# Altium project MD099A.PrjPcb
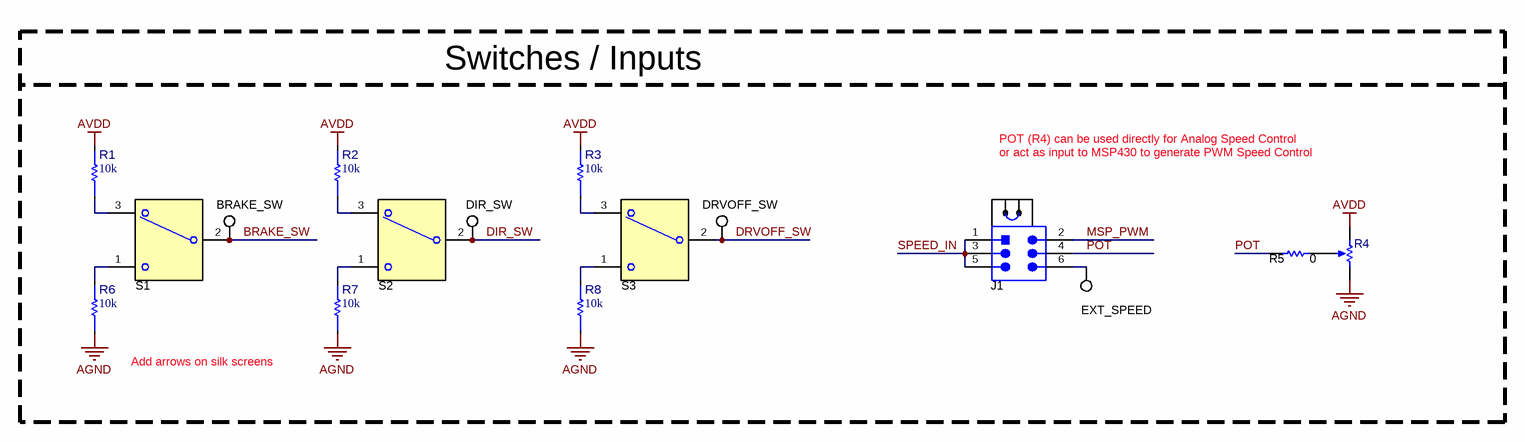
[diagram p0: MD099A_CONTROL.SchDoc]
TID: N/A; TechSupport: http://www.ti.com/support; SCH_Rev: Rev A; ProjectVariant: EVM_Orderable; PRJ_Title: MCF8315RRYEVM; PRJ_Number: MD099A; PRJ_Engineer: Andy Ampuero; PRJ_Customer: Public Release; PCB_Rev: Rev1.0; PCB_Layout: Andy Ampuero; CopyrightYear: 2024
5 sheets, 152 parts. Net scope: global (net labels, ports and power ports of the same name join across sheets).
Board file: MD099A.PcbDoc
Sheets:
  MD099A_CONTROL.SchDoc
  MD099A_DRIVER.SchDoc
  MD099A_HARDWARE.SchDoc
  MD099A_INTERFACE.SchDoc
  MD099A_POWER_AND_CONNECTORS.SchDoc

## Sheet MD099A_CONTROL.SchDoc
size 431 x 279 mm; Date: Not shown in title block; ApprovedBy: Not shown in title block; CheckedBy: Not shown in title block; Author: Not shown in title block; CompanyName: Not shown in title block; Engineer: Not shown in title block; Organization: Not shown in title block; Address1: Not shown in title block; Address2: Not shown in title block; Address3: Not shown in title block; Address4: Not shown in title block; DocumentNumber: 1; Revision: Use project parameter SCH_Rev; SheetNumber: 2; SheetTotal: 5; PageSetup: Record=PageOptions¦CenterHorizontal=True¦CenterVertical=True¦PrintScale=1.00¦XCorrection=1.00¦YCorrection=1.00¦PrintKind=0¦BorderSize=5000000¦LeftOffset=0¦BottomOffset=0¦Orientation=2¦PaperLength=1000¦PaperWidth=1000¦Scale=100¦PaperSource=15¦PrintQuality=600¦MediaType=1¦DitherType=10¦PaperKind=Letter¦PrintScaleMode=1

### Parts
J1  Header_3x2  [TSW-103-07-G-D]  (value not drawn)
R1  value 10k  [FP-ERA-3ARB103V_0603-MFG]  (hidden comment: ERA-3ARB103V)
R2  value 10k  [FP-ERA-3ARB103V_0603-MFG]  (hidden comment: ERA-3ARB103V)
R3  value 10k  [FP-ERA-3ARB103V_0603-MFG]  (hidden comment: ERA-3ARB103V)
R4  3352T-1-253LF  [Bourns_3352T]  (value not drawn)
R5  ValueDisplayed: 0  [0603L]  (hidden comment: ERJ-3GEY0R00V)
R6  value 10k  [FP-ERA-3ARB103V_0603-MFG]  (hidden comment: ERA-3ARB103V)
R7  value 10k  [FP-ERA-3ARB103V_0603-MFG]  (hidden comment: ERA-3ARB103V)
R8  value 10k  [FP-ERA-3ARB103V_0603-MFG]  (hidden comment: ERA-3ARB103V)
S1  SW_SPDT_COM2_1_3  [SW_B12AP]  (value not drawn)
S2  SW_SPDT_COM2_1_3  [SW_B12AP]  (value not drawn)
S3  SW_SPDT_COM2_1_3  [SW_B12AP]  (value not drawn)
SH-J1  SNT-100-BK-G  [SNT-100-BK-G]  (value not drawn)
TP1  BRAKE_SW  [Keystone5002]
TP2  DIR_SW  [Keystone5002]
TP3  DRVOFF_SW  [Keystone5002]
TP4  EXT_SPEED  [Keystone5002]

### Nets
AGND: R4.3(CW) R6.1 R7.1 R8.1
AVDD: R1.2 R2.2 R3.2 R4.1(CCW)
BRAKE_SW: S1.2(COM) TP1.1
DIR_SW: S2.2(COM) TP2.1
DRVOFF_SW: S3.2(COM) TP3.1
MSP_PWM: J1.2
POT: J1.4 R5.1
SPEED_IN: J1.1 J1.3 J1.5
NetJ1_6: J1.6 TP4.1
NetR1_1: R1.1 S1.3
NetR2_1: R2.1 S2.3
NetR3_1: R3.1 S3.3
NetR4_2: R4.2(WIPER) R5.2
NetR6_2: R6.2 S1.1
NetR7_2: R7.2 S2.1
NetR8_2: R8.2 S3.1

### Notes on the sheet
- Switches / Inputs
- POT (R4) can be used directly for Analog Speed Control
- or act as input to MSP430 to generate PWM Speed Control
- Add arrows on silk screens

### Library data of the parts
J1 = CMP-0075406-2: Header, 100mil, 3x2, Gold, TH; Manufacturer: Samtec; Pitch_mm: 2.54; Gender: Male; Shrouded: N; Row_Count: 2; Current_A: 6.3A; Voltage_V: 550V; Cert_CSA: Y; Green_Lifecycle: Active; Green_REACh: Passed
R1-R3 R6-R8 = CMP-0092019-1: Res Thin Film 0603 10K Ohm 0.1% 1/10W ±10ppm/°C Molded SMD SMD Punched Carrier T/R; Manufacturer: Panasonic; AEC Grade: Grade 0; Power_W: 100mW; VDC_V: 75V; SizeZ_mm: 0.55mm; AEC Qualified: Yes
R4 = CMP-0001776-2: Trimmer Potentiometer, 25kohm, 0.5W, TH; Manufacturer: Bourns
R5 = CMP-0025874-4: RES, 0, 5%, 0.1 W, AEC-Q200 Grade 0, 0603; Manufacturer: Panasonic; Power_W: 100mW; TempCo: 600 ppm/C; Value_Code: 0000; Value: 0; EIA_Code: E24; SizeX_mm: 1.6; SizeY_mm: 0.8; SizeZ_mm: 1; Value2: 0.1W; SizeArea_mm2: 1.28; AEC Qualified: Y; VDC_V: 50V; AEC Category: Q200; SizeAreaWB_mm2: 4.68
S1-S3 = CMP-0002155-2: SWITCH TOGGLE SPDT 0.4VA 28V; PartNumber: B12AP; Manufacturer: NKK Switches; SwitchFunction: On-On; PositionCount: 2; CurrentRating_mA: 100A
SH-J1 = CMP-0003623-3: Shunt, 100mil, Gold plated, Black; Alternate PartNumber: 969102-0000-DA; Manufacturer: Samtec; Alternate Manufacturer: 3M; Value: 1x2
TP1-TP4 = CMP-0055139-1: Test Point, Miniature, White, TH; Manufacturer: Keystone; CNHeader: FALSE; Green_Lifecycle: Active; Green_REACh: Passed; ContactFinish: Silver; CT: TRUE

## Sheet MD099A_DRIVER.SchDoc
size 431 x 279 mm; Date: Not shown in title block; ApprovedBy: Not shown in title block; CheckedBy: Not shown in title block; Author: Not shown in title block; CompanyName: Not shown in title block; Engineer: Not shown in title block; Organization: Not shown in title block; Address1: Not shown in title block; Address2: Not shown in title block; Address3: Not shown in title block; Address4: Not shown in title block; DocumentNumber: 2; Revision: Use project parameter SCH_Rev; SheetNumber: 3; SheetTotal: 5; PageSetup: Record=PageOptions¦CenterHorizontal=True¦CenterVertical=True¦PrintScale=1.00¦XCorrection=1.00¦YCorrection=1.00¦PrintKind=0¦BorderSize=5000000¦LeftOffset=0¦BottomOffset=0¦Orientation=2¦PaperLength=1000¦PaperWidth=1000¦Scale=100¦PaperSource=15¦PrintQuality=600¦MediaType=1¦DitherType=10¦PaperKind=Letter¦PrintScaleMode=1
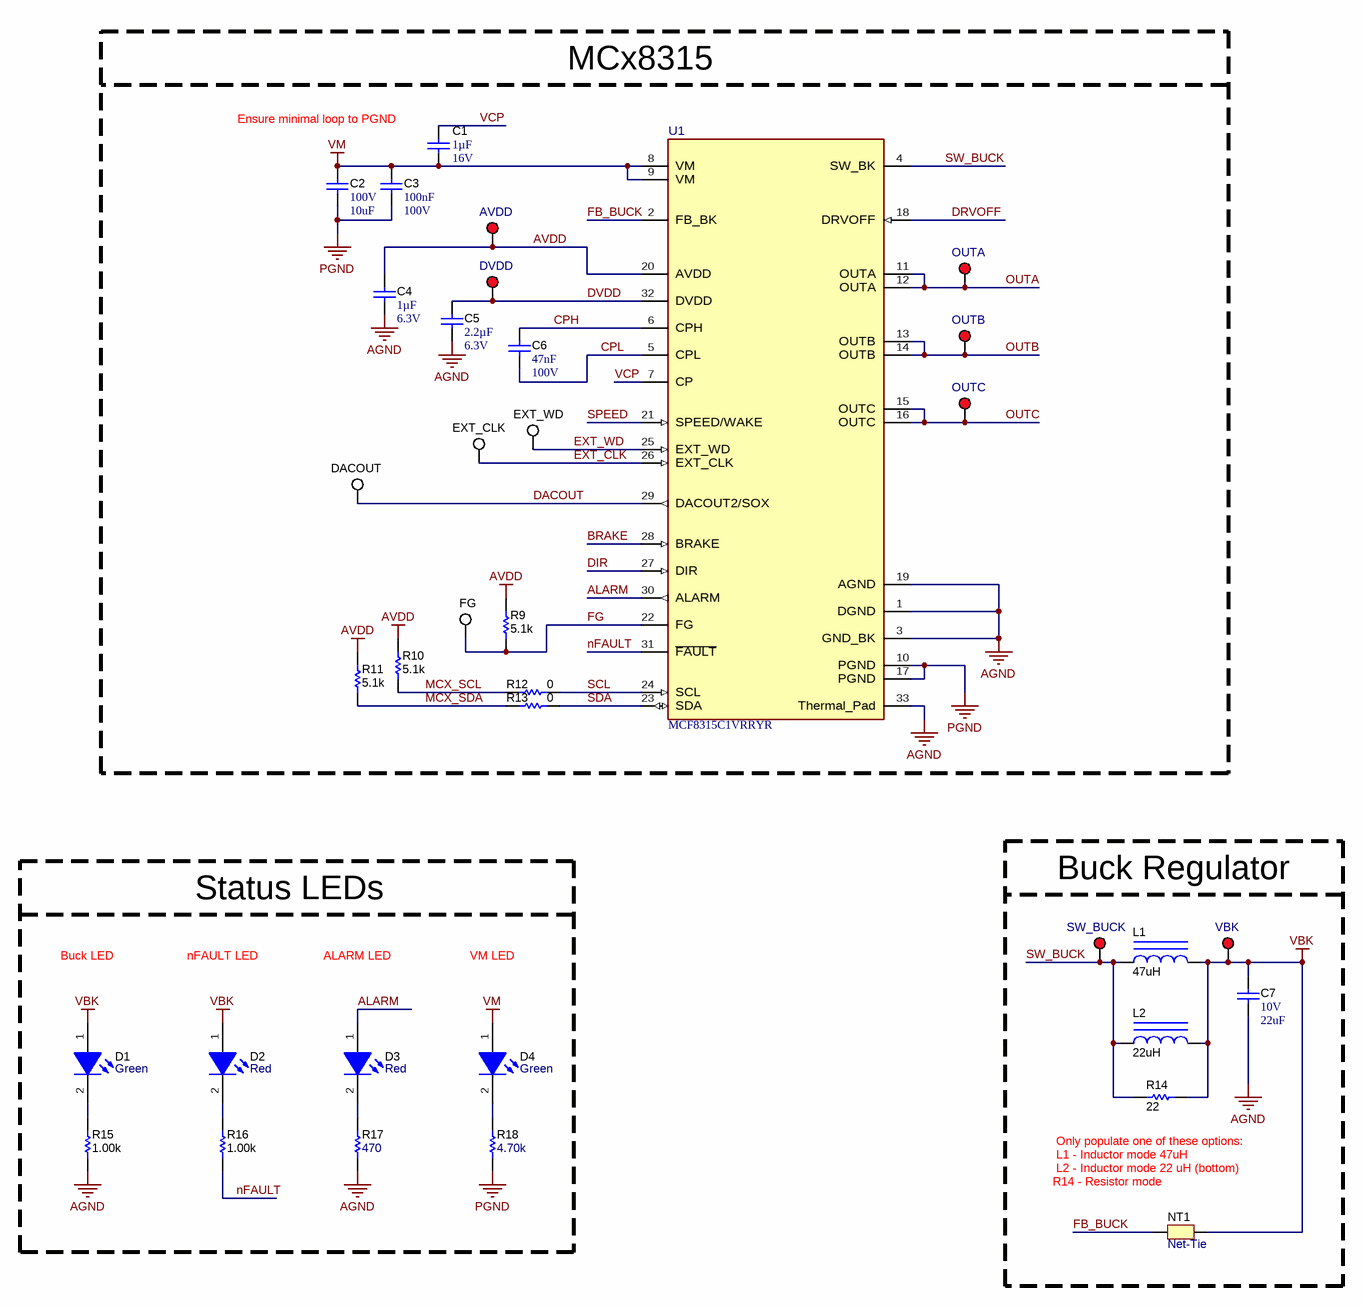
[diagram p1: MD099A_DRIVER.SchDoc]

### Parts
C1  Cap_F: 1µF  VDC_V: 16V  [0603L]  (hidden comment: EMK107B7105KAHT)
C2  VDC_V: 100V  ValueDisplayed: 10uF  [2220_280L]  (hidden comment: 22201C106MAT2A)
C3  Cap_F: 100nF  VDC_V: 100V  [0603L]  (hidden comment: GRM188R72A104KA35D)
C4  Cap_F: 1µF  VDC_V: 6.3V  [0603L]  (hidden comment: C0603C105K9RACAUTO)
C5  Cap_F: 2.2µF  VDC_V: 6.3V  [0603L]  (hidden comment: GCM188R70J225KE22D)
C6  Cap_F: 47nF  VDC_V: 100V  [0805L]  (hidden comment: CGA4J2X7R2A473K125AA)
C7  VDC_V: 10V  ValueDisplayed: 22uF  [1206_180L]  (hidden comment: GRM31CR71A226KE15L)
D1  value Green  [LTST-C170KGKT_Green]  (hidden comment: LTST-C170KGKT)
D2  value Red  [LED_LTST-C170_Red]  (hidden comment: LTST-C170KRKT)
D3  value Red  [LED_LTST-C170_Red]  (hidden comment: LTST-C170KRKT)
D4  value Green  [LTST-C170KGKT_Green]  (hidden comment: LTST-C170KGKT)
L1  ValueDisplayed: 47uH  [WE-MAIA_3015]  (hidden comment: 78438335470)
L2  ValueDisplayed: 22uH  [WE-MAIA_3015]  (hidden comment: 78438335220)
NT1  Net-Tie  [Net-Tie_10mil]  (net tie, no BOM)
R9  ValueDisplayed: 5.1k  [0603L]  (hidden comment: CRCW06035K10JNEA)
R10  ValueDisplayed: 5.1k  [0603L]  (hidden comment: CRCW06035K10JNEA)
R11  ValueDisplayed: 5.1k  [0603L]  (hidden comment: CRCW06035K10JNEA)
R12  ValueDisplayed: 0  [0603L]  (hidden comment: ERJ-3GEY0R00V)
R13  ValueDisplayed: 0  [0603L]  (hidden comment: ERJ-3GEY0R00V)
R14  ValueDisplayed: 22  [2512]  (hidden comment: CRCW251222R0JNEGHP)
R15  ValueDisplayed: 1.00k  [0603L]  (hidden comment: RC0603FR-071KL)
R16  ValueDisplayed: 1.00k  [0603]  (hidden comment: RC0603FR-071KL)
R17  ValueDisplayed: 470  [0603]  (hidden comment: RC0603JR-07470RL)
R18  ValueDisplayed: 4.70k  [0603L]  (hidden comment: RT0603BRD074K7L)
TP5  AVDD  [Keystone5000]
TP6  DVDD  [Keystone5000]
TP7  OUTA  [Keystone5000]
TP8  OUTB  [Keystone5000]
TP9  OUTC  [Keystone5000]
TP10  EXT_WD  [Keystone5002]
TP11  EXT_CLK  [Keystone5002]
TP12  DACOUT  [Keystone5002]
TP13  FG  [Keystone5002]
TP14  SW_BUCK  [Keystone5000]
TP15  VBK  [Keystone5000]
U1  MCF8315C1VRRYR  [RRY0032A-MFG]

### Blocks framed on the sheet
MCx8315: C1-C6 R9-R13 TP5-TP13 U1
Buck Regulator: C7 L1 L2 NT1 R14 TP14 TP15
Status LEDs: D1-D4 R15-R18

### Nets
AGND: C4.1 C5.1 C7.2 R15.1 R17.1 U1.1(DGND) U1.3(GND_BK) U1.19(AGND) U1.33(Thermal_Pad)
AVDD: C4.2 R9.2 R10.1 R11.1 TP5.1 U1.20(AVDD)
PGND: C2.2 C3.2 R18.1 U1.10(PGND) U1.17(PGND)
VBK: C7.1 D1.1(A) D2.1(A) L1.2 L2.2 NT1.2 R14.2 TP15.1
VM: C1.2 C2.1 C3.1 D4.1(A) U1.8(VM) U1.9(VM)
ALARM: D3.1(A) U1.30(ALARM)
BRAKE: U1.28(BRAKE)
CPH: C6.1 U1.6(CPH)
CPL: C6.2 U1.5(CPL)
DACOUT: TP12.1 U1.29(DACOUT2/SOX)
DIR: U1.27(DIR)
DRVOFF: U1.18(DRVOFF)
DVDD: C5.2 TP6.1 U1.32(DVDD)
EXT_CLK: TP11.1 U1.26(EXT_CLK)
EXT_WD: TP10.1 U1.25(EXT_WD)
FB_BUCK: NT1.1 U1.2(FB_BK)
FG: R9.1 TP13.1 U1.22(FG)
MCX_SCL: R10.2 R12.1
MCX_SDA: R11.2 R13.1
nFAULT: R16.1 U1.31(~{FAULT})
OUTA: TP7.1 U1.11(OUTA) U1.12(OUTA)
OUTB: TP8.1 U1.13(OUTB) U1.14(OUTB)
OUTC: TP9.1 U1.15(OUTC) U1.16(OUTC)
SCL: R12.2 U1.24(SCL)
SDA: R13.2 U1.23(SDA)
SPEED: U1.21(SPEED/WAKE)
SW_BUCK: L1.1 L2.1 R14.1 TP14.1 U1.4(SW_BK)
VCP: C1.1 U1.7(CP)
NetD1_2: D1.2(K) R15.2
NetD2_2: D2.2(K) R16.2
NetD3_2: D3.2(K) R17.2
NetD4_2: D4.2(K) R18.2

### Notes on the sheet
- Ensure minimal loop to PGND
- Buck LED
- nFAULT LED
- ALARM LED
- VM LED
- (near NT1) R14 - Resistor mode
- L1 - Inductor mode 47uH
- L2 - Inductor mode 22 uH (bottom)
- (near R14) Only populate one of these options:

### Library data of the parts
C1 = CMP-0080104-1: CAP, CERM, 1 µF, 16 V,+/- 10%, X7R, AEC-Q200 Grade 1, 0603; Manufacturer: Taiyo Yuden; SizeAreaWB_mm2: 4.68; SizeArea_mm2: 1.28; AEC Qualified: Y; AEC Category: Q200; Value: 1uF; TaMax_C: 125°C; SizeZ_mm: 1; Polarized: N; TaMin_C: -55°C; SizeY_mm: 0.8; U/M: EA; SizeX_mm: 1.6; Cap_Case: 0603
C2 = CMP-0009304-2: CAP, CERM, 10 uF, 100 V, +/- 20%, X7R, 2220; Manufacturer: AVX; TaMin_C: -55°C; Polarized: N; SizeAreaWB_mm2: 53.9; Value1: Unknown; U/M: EA; Value: 10uF; TaMax_C: 125°C; SizeZ_mm: 2.8; SizeX_mm: 5.7; SizeY_mm: 5; Cap_Case: 2220; SizeArea_mm2: 28.5; Cap_F: 10µF; AEC Category: Q200
C3 = CMP-0007469-4: CAP, CERM, 0.1 uF, 100 V, +/- 10%, X7R, 0603; Manufacturer: MuRata; TaMin_C: -55°C; TaMax_C: 125°C; SizeY_mm: 0.8; ValueDisplayed: 0.1uF; Cap_Case: 0603; SizeZ_mm: 1; Polarized: N; Value1: Unknown; U/M: EA; SizeAreaWB_mm2: 4.68; AEC Category: Q200; SizeArea_mm2: 1.28; Value: 0.1uF; SizeX_mm: 1.6
C4 = CMP-0086190-1: CAP, CERM, 1 µF, 6.3 V,+/- 10%, X7R, AEC-Q200 Grade 1, 0603; Manufacturer: Kemet; SizeArea_mm2: 1.28; Cap_Case: 0603; SizeY_mm: 0.8; AEC Category: Q200; AEC Qualified: Y; TaMax_C: 125°C; SizeZ_mm: 1; SizeX_mm: 1.6; Polarized: N; Value: 1uF; SizeAreaWB_mm2: 4.68; TaMin_C: -55°C; U/M: EA
C5 = CMP-0007134-5: CAP, CERM, 2.2 uF, 6.3 V, +/- 10%, X7R, AEC-Q200 Grade 1, 0603; Manufacturer: MuRata; TaMin_C: -55°C; Polarized: N; SizeAreaWB_mm2: 4.68; Value1: Unknown; U/M: EA; Value: 2.2uF; TaMax_C: 125°C; SizeZ_mm: 1; SizeX_mm: 1.6; SizeY_mm: 0.8; Cap_Case: 0603; SizeArea_mm2: 1.28; AEC Qualified: Y; AEC Category: Q200
C6 = CMP-0007970-2: CAP, CERM, 0.047 uF, 100 V, +/- 10%, X7R, AEC-Q200 Grade 1, 0805; Manufacturer: TDK; TaMin_C: -55°C; ESR_ohm: 49.089m; Polarized: N; SizeAreaWB_mm2: 6.75; Value1: 0.049089 ohm; U/M: EA; TaMax_C: 125°C; SizeZ_mm: 1.45; SizeX_mm: 2; SizeY_mm: 1.25; Cap_Case: 0805; SizeArea_mm2: 2.5; AEC Qualified: Y; IRMS_A: 963.171mA; AEC Grade: 1; AEC Category: Q200
C7 = CMP-0008959-2: CAP, CERM, 22 uF, 10 V, +/- 10%, X7R, 1206; Manufacturer: MuRata; TaMin_C: -55°C; Polarized: N; SizeAreaWB_mm2: 10.92; Value1: Unknown; U/M: EA; Value: 22uF; TaMax_C: 125°C; SizeZ_mm: 1.8; SizeX_mm: 3.2; SizeY_mm: 1.6; Cap_Case: 1206; SizeArea_mm2: 5.12; Cap_F: 22µF; AEC Category: Q200
D1 D4 = CMP-0002888-2: LED, Green, SMD; Manufacturer: Lite-On; Io_A: 20mA; Value1: W; Vf_V: 2V; Type: AlInGaP
D2 D3 = CMP-0002829-3: LED, Red, SMD; Manufacturer: Lite-On; Io_A: 20mA; SizeAreaWB_mm2: 6.75; Value1: W; SizeZ_mm: 1.2; SizeX_mm: 2; SizeY_mm: 1.25; Vf_V: 2V; SizeArea_mm2: 2.5; Type: AlInGaP
L1 = CMP-0064683-2: Inductor, Shielded, Powdered Iron, 47 uH, 0.39 A, 2.3 ohm, AEC-Q200 Grade 1, SMD; Manufacturer: Wurth Elektronik; Isat: 1.18A @ 20% inductance drop; Irms: 0.39A @ 40C rise; SizeAreaWB_mm2: 16; DCR_ohm: 2.3; Value1: 2.3 ohm; Value: 47uH; Imax_A: 390mA; SizeZ_mm: 1.5; SizeX_mm: 3; Value2: 0.39A; SizeArea_mm2: 9; Ind_H: 47µH; AEC Qualified: Y; AEC Grade: 1; AEC Category: Q200
L2 = CMP-0064681-2: Inductor, Shielded, Powdered Iron, 22 uH, 0.6 A, 1.04 ohm, AEC-Q200 Grade 1, SMD; Manufacturer: Wurth Elektronik; Isat: 1.6A @ 20% inductance drop; Irms: 0.6A @ 40C rise; SizeAreaWB_mm2: 16; DCR_ohm: 1.04; Value: 22uH; Imax_A: 600mA; SizeZ_mm: 1.5; SizeX_mm: 3; Value2: 0.6A; SizeArea_mm2: 9; Ind_H: 22µH; AEC Qualified: Y; AEC Grade: 1; AEC Category: Q200
NT1 = CMP-0078142-4: Single point connection between nets.
R9-R11 = CMP-0025830-4: RES, 5.1 k, 5%, 0.1 W, AEC-Q200 Grade 0, 0603; Manufacturer: Vishay-Dale; Power_W: 100mW; TempCo: 200 ppm/C; Value_Code: 5k10; Value: 5.1k; EIA_Code: E24; SizeX_mm: 1.6; SizeY_mm: 0.8; SizeZ_mm: 1; Value2: 0.1W; SizeArea_mm2: 1.28; AEC Qualified: Y; VDC_V: 75V; AEC Category: Q200; AEC Grade: 0
R12 R13 = CMP-0025874-4: as R5 on sheet MD099A_CONTROL
R14 = CMP-0015919-3: RES, 22, 5%, 1.5 W, AEC-Q200 Grade 0, 2512; Manufacturer: Vishay-Dale; Power_W: 1.5W; TempCo: 200 ppm/C; Value_Code: 22R0; Value: 22; EIA_Code: E24; SizeX_mm: 6.3; SizeY_mm: 3.2; SizeZ_mm: 0.71; SizeArea_mm2: 20.16; AEC Qualified: Y; VDC_V: 500V; AEC Category: Q200; AEC Grade: 0
R15 R16 = CMP-0022895-5: RES, 1.00 k, 1%, 0.1 W, 0603; Manufacturer: Yageo; Power_W: 100mW; TempCo: 100 ppm/C; Value_Code: 1k00; Value: 1.00k; EIA_Code: E96; Res_ohm: 1k; SizeX_mm: 1.6; SizeY_mm: 0.8; SizeZ_mm: 1; Value2: 0.1W; SizeArea_mm2: 1.28; AEC Qualified: N; VDC_V: 75V; AEC Category: Q200; SizeAreaWB_mm2: 4.68
R17 = CMP-0025924-5: RES, 470, 5%, 0.1 W, 0603; Manufacturer: Yageo; Power_W: 100mW; TempCo: 100 ppm/C; Value_Code: 470R; Value: 470; EIA_Code: E24; SizeX_mm: 1.6; SizeY_mm: 0.8; SizeZ_mm: 1; Value2: 0.1W; SizeArea_mm2: 1.28; AEC Qualified: N; VDC_V: 75V; AEC Category: Q200; SizeAreaWB_mm2: 4.68
R18 = CMP-0024300-2: RES, 4.70 k, 0.1%, 0.1 W, 0603; Manufacturer: Yageo America; Power_W: 100mW; TempCo: 25 ppm/C; Value_Code: 4k70; U/M: EA; Value: 4.70k; EIA_Code: E192; Res_ohm: 4.7k; SizeX_mm: 1.6; SizeY_mm: 0.8; SizeZ_mm: 1; Value2: 0.1W; SizeArea_mm2: 1.28; VDC_V: 75V; AEC Category: Q200
TP5-TP9 TP14 TP15 = CMP-0055137-1: Test Point, Miniature, Red, TH; PartNumber: 5000; Manufacturer: Keystone; ContactFinish: Silver; CNHeader: FALSE; CT: TRUE; Green_Lifecycle: Active; Green_REACh: Passed
TP10-TP13 = CMP-0055139-1: as TP1 on sheet MD099A_CONTROL
U1 = CMP-0001322-1: Sensorless Field Oriented Control (FOC) Integrated FET BLDC Driver, WQFN32; Manufacturer: Texas Instruments; SizeZ_mm: 0.8mm; Max Supply Voltage: 35V; Min Supply Voltage: 4.5V; Motor Type: Brushless DC; Nominal Supply Current: 11-28mA; Number Of Outputs: 3; Standoff Height: 0mm; TaMax_C: +125°C; TaMin_C: -40°C; TJmax_C: +150°C

## Sheet MD099A_HARDWARE.SchDoc
size 431 x 279 mm; Date: Not shown in title block; ApprovedBy: Not shown in title block; CheckedBy: Not shown in title block; Author: Not shown in title block; CompanyName: Not shown in title block; Engineer: Not shown in title block; Organization: Not shown in title block; Address1: Not shown in title block; Address2: Not shown in title block; Address3: Not shown in title block; Address4: Not shown in title block; DocumentNumber: 3; Revision: Use project parameter SCH_Rev; SheetNumber: 5; SheetTotal: 5; PageSetup: Record=PageOptions¦CenterHorizontal=True¦CenterVertical=True¦PrintScale=1.00¦XCorrection=1.00¦YCorrection=1.00¦PrintKind=0¦BorderSize=5000000¦LeftOffset=0¦BottomOffset=0¦Orientation=2¦PaperLength=1000¦PaperWidth=1000¦Scale=100¦PaperSource=15¦PrintQuality=600¦MediaType=1¦DitherType=10¦PaperKind=Letter¦PrintScaleMode=1
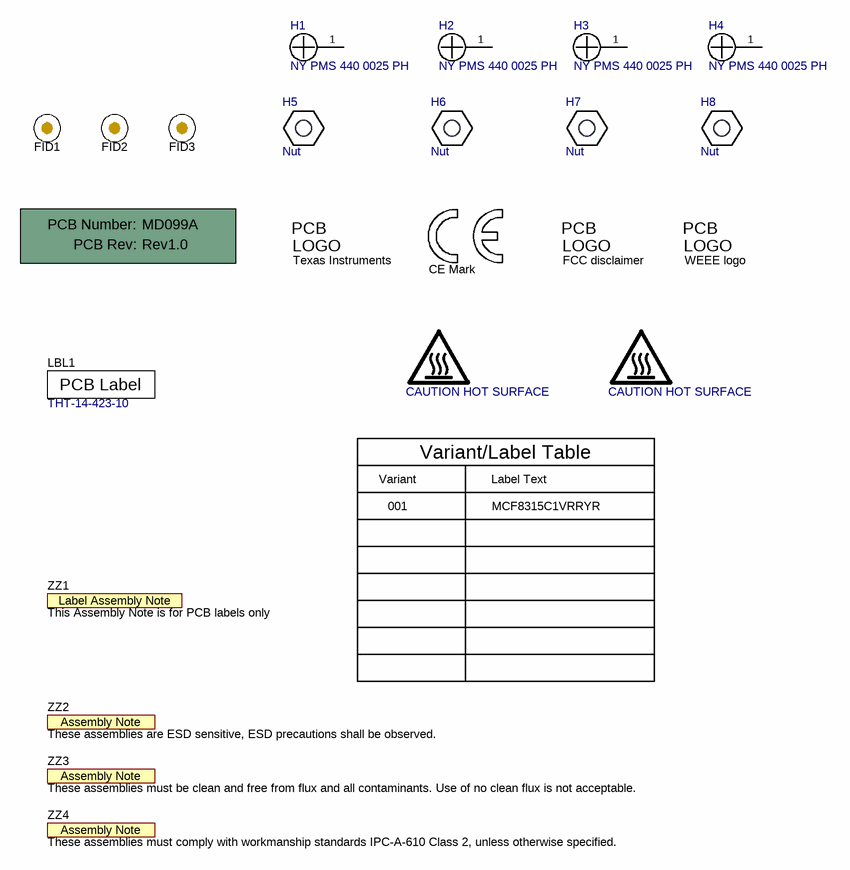
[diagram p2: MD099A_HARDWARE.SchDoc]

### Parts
!PCB1  Printed Circuit Board  (value not drawn)  (mechanical)
FID1  Fiducial  [Fiducial10-20]  (value not drawn)
FID2  Fiducial  [Fiducial10-20]  (value not drawn)
FID3  Fiducial  [Fiducial10-20]  (value not drawn)
H1  NY PMS 440 0025 PH  [NY PMS 440 0025 PH]
H2  NY PMS 440 0025 PH  [NY PMS 440 0025 PH]
H3  NY PMS 440 0025 PH  [NY PMS 440 0025 PH]
H4  NY PMS 440 0025 PH  [NY PMS 440 0025 PH]
H5  Nut  [Keystone_1902C]
H6  Nut  [Keystone_1902C]
H7  Nut  [Keystone_1902C]
H8  Nut  [Keystone_1902C]
LBL1  THT-14-423-10  [Label_650x200]
Logo1  CE Mark  [CE_Mark_5mm]  (no BOM)
Logo2  Texas Instruments  [TI_Stacked_Overlay_Small]  (no BOM)
Logo3  FCC disclaimer  [FCC_disclaimer]  (no BOM)
Logo4  WEEE logo  [WEEE_Minimum]  (no BOM)
LOGO5  CAUTION HOT SURFACE  [IEC_HotSurface_Small]  (no BOM)
LOGO6  CAUTION HOT SURFACE  [IEC_HotSurface_Small]  (no BOM)
ZZ1  This Assembly Note is for PCB labels only  [AssemblyNoteLabel]  (no BOM)
ZZ2  These assemblies are ESD sensitive, ESD precautions shall be observed.  [AssemblyNote]  (no BOM)
ZZ3  These assemblies must be clean and free from flux and all contaminants. Use of no clean flux is not acceptable.  [AssemblyNote]  (no BOM)
ZZ4  These assemblies must comply with workmanship standards IPC-A-610 Class 2, unless otherwise specified.  [AssemblyNote]  (no BOM)

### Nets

Not connected (* = marked no-connect by the designer): H1 1; H2 1; H3 1; H4 1

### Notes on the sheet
- Variant
- Variant/Label Table
- Label Text
- 001
- MCF8315C1VRRYR

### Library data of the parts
!PCB1 = CMP-0003618-2: Manufacturer: Any; PartNumber: MD099A
FID1-FID3 = CMP-0077181-1: Fiducial mark.  There is nothing to buy or mount.
H1-H4 = CMP-0003617-1: Machine Screw, Round, #4-40 x 1/4, Nylon, Philips panhead; Manufacturer: B&F Fastener Supply; CompType: Hardware
H5-H8 = CMP-0003610-1: Standoff, Hex, 0.5"L #4-40 Nylon; Manufacturer: Keystone; PartNumber: 1902C; CompType: Hardware
LBL1 = CMP-0003625-1: Manufacturer: Brady
Logo1 = CMP-0074844-1: SymbolCreator: a0412235
Logo2 = CMP-0074838-1: Texas Instrument Corporate Signature; SymbolCreator: a0412235; Lib Reference: TI_Logo; Library Reference: Logo
Logo3 = CMP-0074847-1: FCC_disclaimer; Library Reference: Logo
Logo4 = CMP-0074769-1
LOGO5 LOGO6 = CMP-0074837-1: IEC 61010-1 Hot Surface Warning; SymbolCreator: a0412235
ZZ1 = CMP-0003616-3
ZZ2 = CMP-0077236-1
ZZ3 = CMP-0077237-1
ZZ4 = CMP-0077238-1

## Sheet MD099A_INTERFACE.SchDoc
size 431 x 279 mm; Date: Not shown in title block; ApprovedBy: Not shown in title block; CheckedBy: Not shown in title block; Author: Not shown in title block; CompanyName: Not shown in title block; Engineer: Not shown in title block; Organization: Not shown in title block; Address1: Not shown in title block; Address2: Not shown in title block; Address3: Not shown in title block; Address4: Not shown in title block; DocumentNumber: 4; Revision: Use project parameter SCH_Rev; SheetNumber: 1; SheetTotal: 5; PageSetup: Record=PageOptions¦CenterHorizontal=True¦CenterVertical=True¦PrintScale=1.00¦XCorrection=1.00¦YCorrection=1.00¦PrintKind=0¦BorderSize=5000000¦LeftOffset=0¦BottomOffset=0¦Orientation=2¦PaperLength=1000¦PaperWidth=1000¦Scale=100¦PaperSource=15¦PrintQuality=600¦MediaType=1¦DitherType=10¦PaperKind=Letter¦PrintScaleMode=1
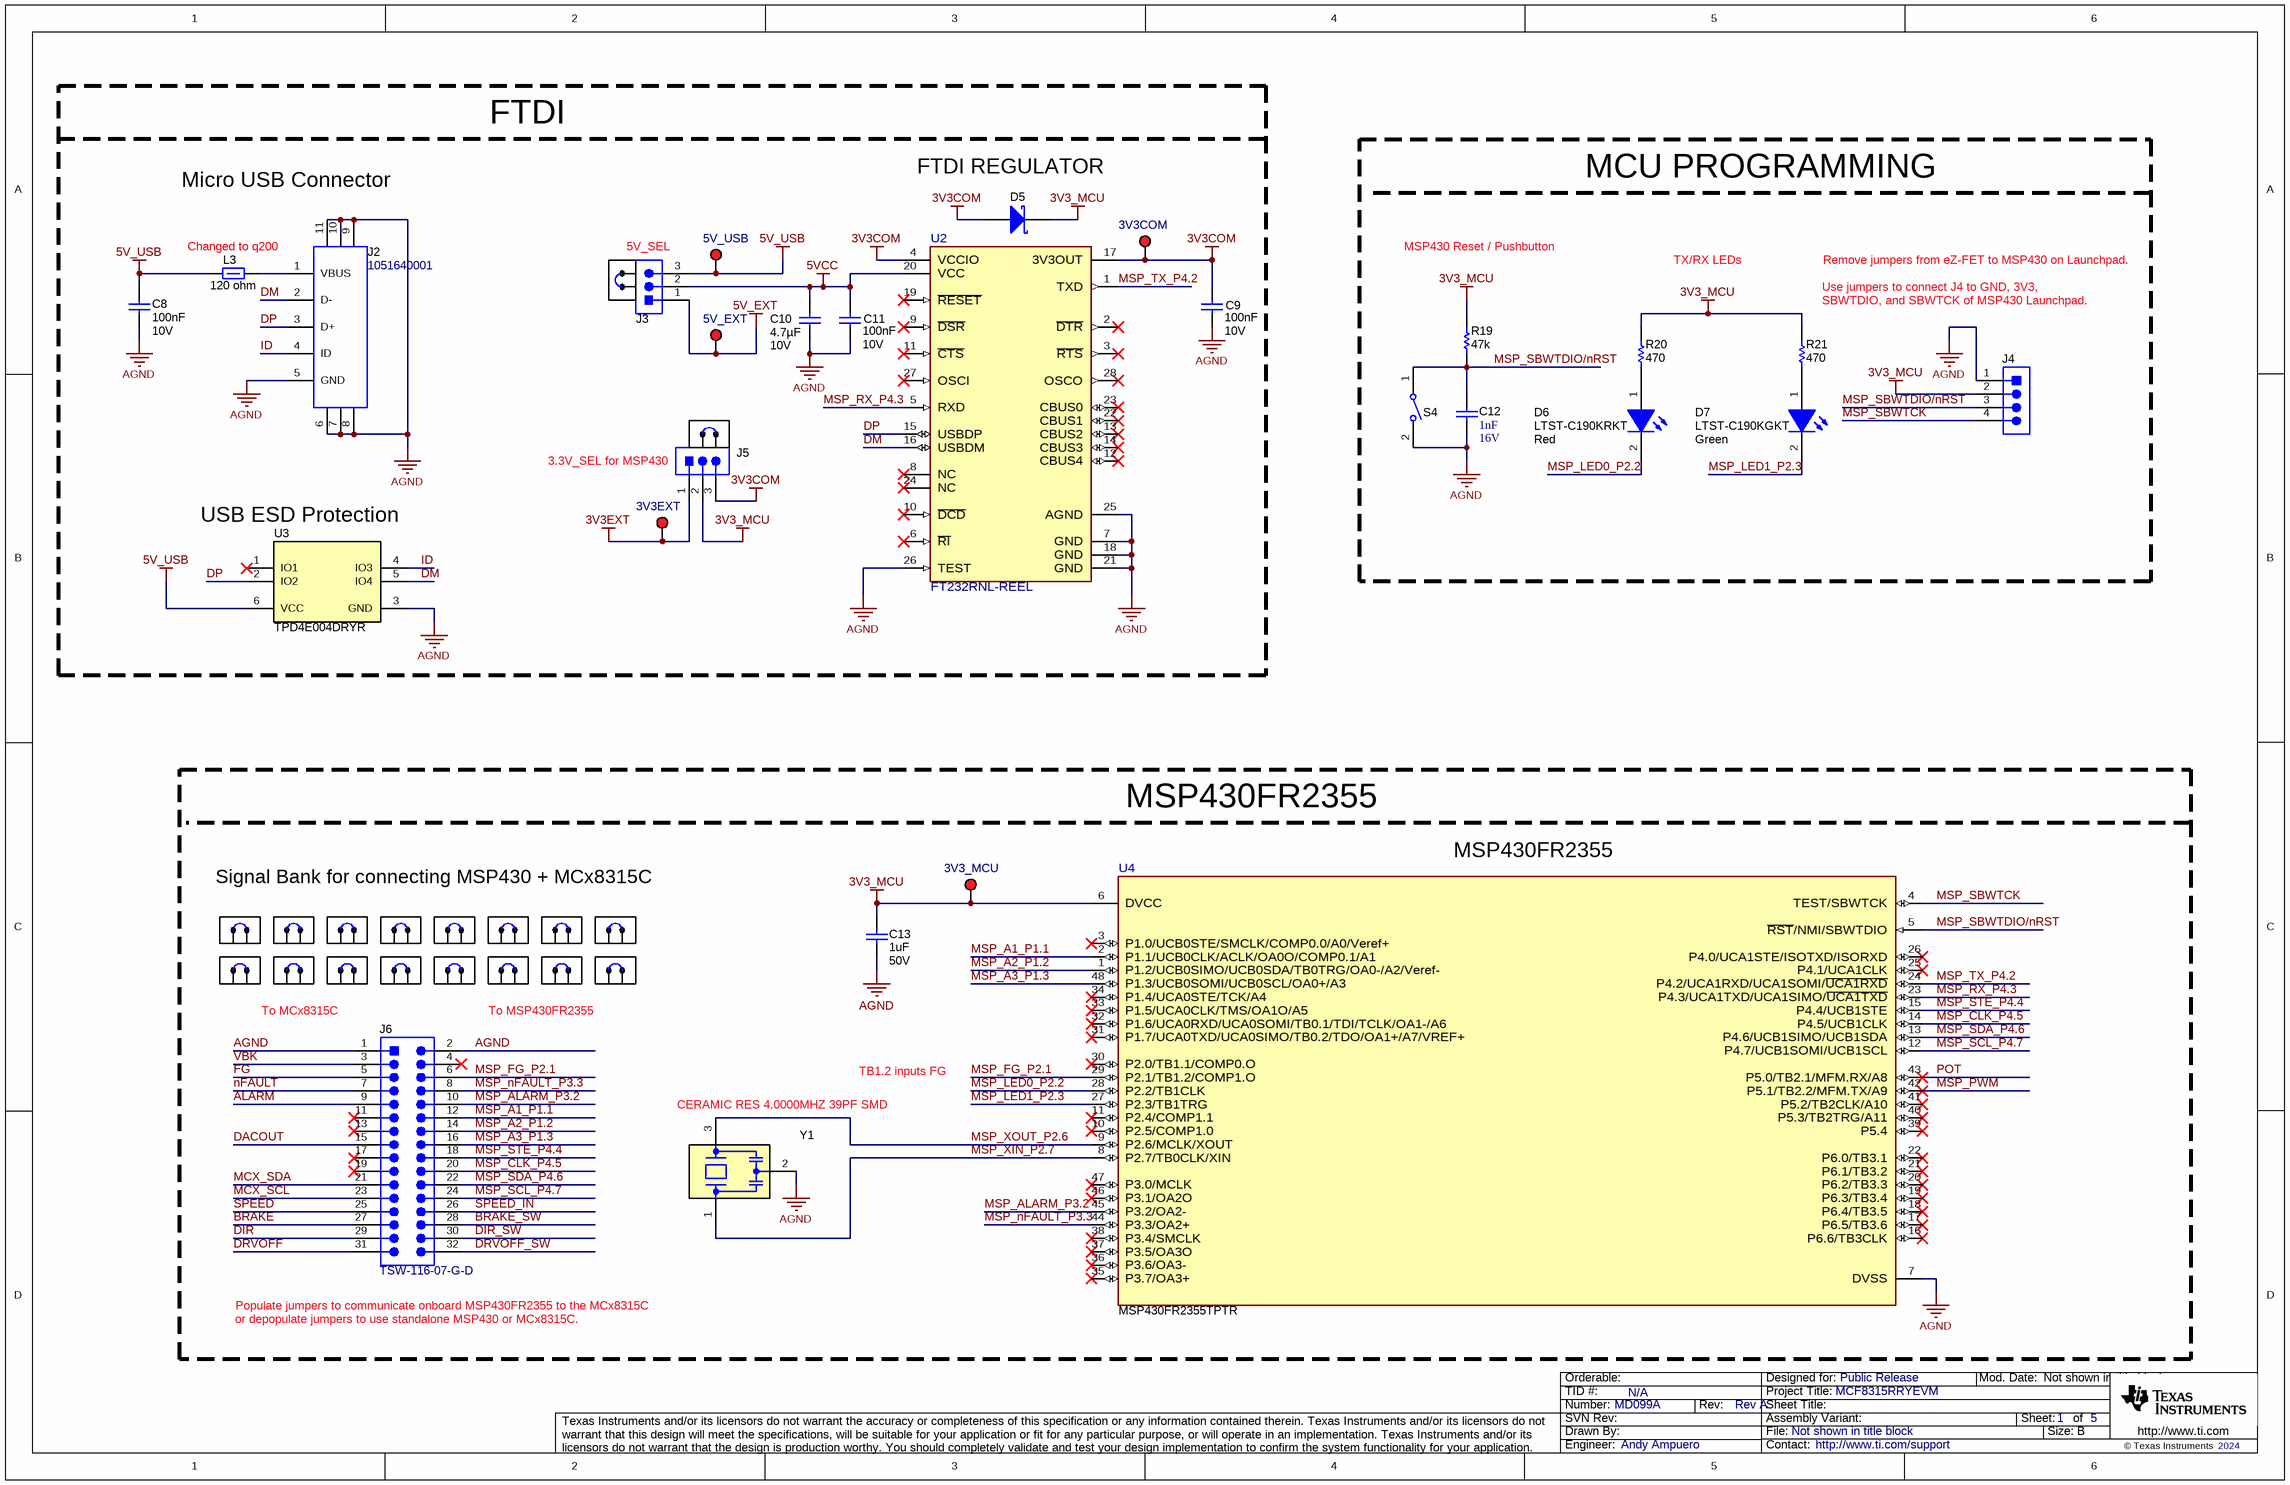
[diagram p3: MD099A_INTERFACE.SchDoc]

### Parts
C8  Cap_F: 100nF  VDC_V: 10V  [0603L]  (hidden comment: 0603ZC104KAT2A)
C9  Cap_F: 100nF  VDC_V: 10V  [0603L]  (hidden comment: 0603ZC104KAT2A)
C10  Cap_F: 4.7µF  VDC_V: 10V  [0603L]  (hidden comment: GRM188Z71A475ME15D)
C11  Cap_F: 100nF  VDC_V: 10V  [0603L]  (hidden comment: 0603ZC104KAT2A)
C12  Cap_F: 1nF  VDC_V: 16V  [0603L]  (hidden comment: 885012206034)
C13  ValueDisplayed: 1uF  VDC_V: 50V  [0805L]  (hidden comment: 885012207103)
D5  BAT165E6327HTSA1  [SOD-323]  (value not drawn)
D6  LTST-C190KRKT  value Red  [LED_LTST-C190_Red]
D7  LTST-C190KGKT  value Green  [LED_LTST-C190_G]
J2  1051640001  [Molex_1051640001]
J3  Header_3x1  [PBC03SAAN]  (value not drawn)
J4  TSW-104-07-G-S  [TSW-104-07-G-S]  (value not drawn)
J5  Header_3x1  [PBC03SAAN]  (value not drawn)
J6  TSW-116-07-G-D  [TSW-116-07-G-D]
L3  DCR_ohm: 120 ohm  [0603L]  (hidden comment: BLM18SG121TZ1D)
R19  ValueDisplayed: 47k  [0603L]  (hidden comment: RC0603JR-0747KL)
R20  ValueDisplayed: 470  [0603L]  (hidden comment: RC0603JR-07470RL)
R21  ValueDisplayed: 470  [0603L]  (hidden comment: RC0603JR-07470RL)
S4  SW_SPST-single  [SW_434121025816]  (value not drawn)
SH-J2  SNT-100-BK-G  [SNT-100-BK-G]  (value not drawn)
SH-J3  SNT-100-BK-G  [SNT-100-BK-G]  (value not drawn)
SH-J4  SNT-100-BK-G  [SNT-100-BK-G]  (value not drawn)
SH-J5  SNT-100-BK-G  [SNT-100-BK-G]  (value not drawn)
SH-J6  SNT-100-BK-G  [SNT-100-BK-G]  (value not drawn)
SH-J7  SNT-100-BK-G  [SNT-100-BK-G]  (value not drawn)
SH-J8  SNT-100-BK-G  [SNT-100-BK-G]  (value not drawn)
SH-J9  SNT-100-BK-G  [SNT-100-BK-G]  (value not drawn)
SH-J10  SNT-100-BK-G  [SNT-100-BK-G]  (value not drawn)
SH-J11  SNT-100-BK-G  [SNT-100-BK-G]  (value not drawn)
SH-J12  SNT-100-BK-G  [SNT-100-BK-G]  (value not drawn)
SH-J13  SNT-100-BK-G  [SNT-100-BK-G]  (value not drawn)
SH-J14  SNT-100-BK-G  [SNT-100-BK-G]  (value not drawn)
SH-J15  SNT-100-BK-G  [SNT-100-BK-G]  (value not drawn)
SH-J16  SNT-100-BK-G  [SNT-100-BK-G]  (value not drawn)
SH-J17  SNT-100-BK-G  [SNT-100-BK-G]  (value not drawn)
SH-J18  SNT-100-BK-G  [SNT-100-BK-G]  (value not drawn)
SH-J19  SNT-100-BK-G  [SNT-100-BK-G]  (value not drawn)
TP16  3V3COM  [Keystone5000]
TP17  5V_USB  [Keystone5000]
TP18  5V_EXT  [Keystone5000]
TP19  3V3EXT  [Keystone5000]
TP20  3V3_MCU  [Keystone5000]
U2  FT232RNL-REEL  [FP-FT232RNL-REEL_SSOP28-MFG]
U3  TPD4E004DRYR  [DRY0006A]
U4  MSP430FR2355TPTR  [PT0048A-MFG]
Y1  CSTCR4M00G55B-R0  [Murata_CSTCR_G]  (value not drawn)

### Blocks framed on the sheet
FTDI: C8-C11 D5 J2 J3 J5 L3 SH-J2 SH-J3 TP16-TP19 U2 U3
MCU PROGRAMMING: C12 D6 D7 J4 R19-R21 S4
MSP430FR2355: C13 J6 SH-J4-SH-J19 TP20 U4 Y1

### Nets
3V3_MCU: C13.1 D5.1(K) J4.2 J5.2 R19.2 R20.2 R21.2 TP20.1 U4.6(DVCC)
3V3COM: C9.1 D5.2(A) J5.3 TP16.1 U2.4(VCCIO) U2.17(3V3OUT)
3V3EXT: J5.1 TP19.1
5V_EXT: J3.1 TP18.1
5V_USB: C8.1 J3.3 L3.1 TP17.1 U3.6(VCC)
5VCC: C10.2 C11.1 J3.2 U2.20(VCC)
AGND: C8.2 C9.2 C10.1 C11.2 C12.2 C13.2 J2.5(GND) J2.6 J2.7 J2.8 J2.9 J2.10 J2.11 J4.1 J6.1 J6.2 S4.2 U2.7(GND) U2.18(GND) U2.21(GND) U2.25(AGND) U2.26(TEST) U3.3(GND) U4.7(DVSS) Y1.2(GND)
VBK: J6.3
ALARM: J6.9
BRAKE: J6.27
BRAKE_SW: J6.28
DACOUT: J6.15
DIR: J6.29
DIR_SW: J6.30
DM: J2.2(D-) U2.16(USBDM) U3.5(IO4)
DP: J2.3(D+) U2.15(USBDP) U3.2(IO2)
DRVOFF: J6.31
DRVOFF_SW: J6.32
FG: J6.5
ID: J2.4(ID) U3.4(IO3)
MCX_SCL: J6.23
MCX_SDA: J6.21
MSP_A1_P1.1: J6.12 U4.2(P1.1/UCB0CLK/ACLK/OA0O/COMP0.1/A1)
MSP_A2_P1.2: J6.14 U4.1(P1.2/UCB0SIMO/UCB0SDA/TB0TRG/OA0-/A2/Veref-)
MSP_A3_P1.3: J6.16 U4.48(P1.3/UCB0SOMI/UCB0SCL/OA0+/A3)
MSP_ALARM_P3.2: J6.10 U4.45(P3.2/OA2-)
MSP_CLK_P4.5: J6.20 U4.14(P4.5/UCB1CLK)
MSP_FG_P2.1: J6.6 U4.29(P2.1/TB1.2/COMP1.O)
MSP_LED0_P2.2: D6.2(K) U4.28(P2.2/TB1CLK)
MSP_LED1_P2.3: D7.2(K) U4.27(P2.3/TB1TRG)
MSP_nFAULT_P3.3: J6.8 U4.44(P3.3/OA2+)
MSP_PWM: U4.42(P5.1/TB2.2/MFM.TX/A9)
MSP_RX_P4.3: U2.5(RXD) U4.23(P4.3/UCA1TXD/UCA1SIMO/~{UCA1TXD})
MSP_SBWTCK: J4.4 U4.4(TEST/SBWTCK)
MSP_SBWTDIO/nRST: C12.1 J4.3 R19.1 S4.1 U4.5(~{RST}/NMI/SBWTDIO)
MSP_SCL_P4.7: J6.24 U4.12(P4.7/UCB1SOMI/UCB1SCL)
MSP_SDA_P4.6: J6.22 U4.13(P4.6/UCB1SIMO/UCB1SDA)
MSP_STE_P4.4: J6.18 U4.15(P4.4/UCB1STE)
MSP_TX_P4.2: U2.1(TXD) U4.24(P4.2/UCA1RXD/UCA1SOMI/~{UCA1RXD})
MSP_XIN_P2.7: U4.8(P2.7/TB0CLK/XIN) Y1.1(In)
MSP_XOUT_P2.6: U4.9(P2.6/MCLK/XOUT) Y1.3(Out)
nFAULT: J6.7
POT: U4.43(P5.0/TB2.1/MFM.RX/A8)
SPEED: J6.25
SPEED_IN: J6.26
NetD6_1: D6.1(A) R20.1
NetD7_1: D7.1(A) R21.1
NetJ2_1: J2.1(VBUS) L3.2

Not connected (* = marked no-connect by the designer): J6 4* 11* 13* 17* 19*; U2 2(~{DTR})* 3(~{RTS})* 6(~{RI})* 8(NC)* 9(~{DSR})* 10(~{DCD})* 11(~{CTS})* 12(CBUS4)* 13(CBUS2)* 14(CBUS3)* 19(~{RESET})* 22(CBUS1)* 23(CBUS0)* 24(NC)* 27(OSCI)* 28(OSCO)*; U3 1(IO1)*; U4 3(P1.0/UCB0STE/SMCLK/COMP0.0/A0/Veref+)* 10(P2.5/COMP1.0)* 11(P2.4/COMP1.1)* 16(P6.6/TB3CLK)* 17(P6.5/TB3.6)* 18(P6.4/TB3.5)* 19(P6.3/TB3.4)* 20(P6.2/TB3.3)* 21(P6.1/TB3.2)* 22(P6.0/TB3.1)* 25(P4.1/UCA1CLK)* 26(P4.0/UCA1STE/ISOTXD/ISORXD)* 30(P2.0/TB1.1/COMP0.O)* 31(P1.7/UCA0TXD/UCA0SIMO/TB0.2/TDO/OA1+/A7/VREF+)* 32(P1.6/UCA0RXD/UCA0SOMI/TB0.1/TDI/TCLK/OA1-/A6)* 33(P1.5/UCA0CLK/TMS/OA1O/A5)* 34(P1.4/UCA0STE/TCK/A4)* 35(P3.7/OA3+)* 36(P3.6/OA3-)* 37(P3.5/OA3O)* 38(P3.4/SMCLK)* 39(P5.4)* 40(P5.3/TB2TRG/A11)* 41(P5.2/TB2CLK/A10)* 46(P3.1/OA2O)* 47(P3.0/MCLK)*

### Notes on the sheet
- (near D5) FTDI REGULATOR
- Micro USB Connector
- (near L3) Changed to q200
- 5V_SEL
- MSP430 Reset / Pushbutton
- TX/RX LEDs
- (near R21) Use jumpers to connect J4 to GND, 3V3,
- SBWTDIO, and SBWTCK of MSP430 Launchpad.
- Remove jumpers from eZ-FET to MSP430 on Launchpad.
- (near J5) 3.3V_SEL for MSP430
- (near U3) USB ESD Protection
- Signal Bank for connecting MSP430 + MCx8315C
- (near U4) MSP430FR2355
- To MCx8315C
- To MSP430FR2355
- (near Y1) CERAMIC RES 4.0000MHZ 39PF SMD
- TB1.2 inputs FG
- (near J6) Populate jumpers to communicate onboard MSP430FR2355 to the MCx8315C
- or depopulate jumpers to use standalone MSP430 or MCx8315C.

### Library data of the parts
C8 C9 C11 = CMP-0006815-4: CAP, CERM, 0.1 uF, 10 V, +/- 10%, X7R, 0603; Manufacturer: AVX; TaMin_C: -55°C; Polarized: N; SizeAreaWB_mm2: 4.68; Value1: Unknown; U/M: EA; Value: 0.1uF; TaMax_C: 125°C; SizeZ_mm: 1; SizeX_mm: 1.6; SizeY_mm: 0.8; Cap_Case: 0603; SizeArea_mm2: 1.28; AEC Category: Q200
C10 = CMP-0007498-4: CAP, CERM, 4.7 uF, 10 V, +/- 20%, X7R, 0603; Manufacturer: MuRata; TaMin_C: -55°C; Polarized: N; SizeAreaWB_mm2: 4.68; Value1: Unknown; U/M: EA; Value: 4.7uF; TaMax_C: 125°C; SizeZ_mm: 1; SizeX_mm: 1.6; SizeY_mm: 0.8; Cap_Case: 0603; SizeArea_mm2: 1.28; AEC Category: Q200
C12 = CMP-0006826-4: CAP, CERM, 1000 pF, 16 V, +/- 10%, X7R, 0603; Manufacturer: Wurth Elektronik; TaMin_C: -55°C; Polarized: N; SizeAreaWB_mm2: 4.68; Value1: Unknown; U/M: EA; Value: 1000pF; TaMax_C: 125°C; SizeZ_mm: 1; SizeX_mm: 1.6; SizeY_mm: 0.8; Cap_Case: 0603; SizeArea_mm2: 1.28; AEC Category: Q200
C13 = CMP-0007696-2: CAP, CERM, 1 uF, 50 V, +/- 10%, X7R, 0805; Manufacturer: Wurth Elektronik; Polarized: N; CompType: Capacitor; Value: 1uF; U/M: EA; Cap_F: 1µF; Value1: Unknown; TaMin_C: -55°C; TaMax_C: 125°C; Cap_Case: 0805; SizeArea_mm2: 2.5; SizeAreaWB_mm2: 6.75; SizeX_mm: 2; SizeY_mm: 1.25; SizeZ_mm: 1.45; AEC Category: Q200
D5 = CMP-0028882-2: Diode, Schottky, 40 V, 0.75 A, AEC-Q101, SOD-323; Manufacturer: Infineon Technologies; Vf_V: 740mV; Value: 40V; Value1: 0.75A; Value2: 0.74V; Io_A: 750mA; TJmax_C: 150°C; AEC Category: Q101; AEC Qualified: Y; Green_Lifecycle: Not Set; Green_REACh: Incomplete; SizeArea_mm2: 3.645; SizeAreaWB_mm2: 8.695; SizeX_mm: 2.7; SizeY_mm: 1.35; SizeZ_mm: 1
D6 = CMP-0078131-2: LED, Red, SMD; Manufacturer: Lite-On; Type: AlInGaP; Ir_A: 10µA; Angle: 130; Power_TotalModule: 62.5mW; Value2: 2V; Green_Lifecycle: Not Set; Io_A: 20mA; Value1: .0625W; Green_REACh: Incomplete; Vr_V: 5V
D7 = CMP-0002840-2: LED, Green, SMD; Manufacturer: Lite-On; Type: AlInGaP; Value2: 2V; Io_A: 30mA; Value1: W; Tjmax_C: 85°C
J2 = CMP-0055311-1: Receptacle, USB 2.0, Micro B, 5 Position, R/A, SMT; Manufacturer: Molex; CNHeader: FALSE; Current_A: 1.8A; Gender: Female; Voltage_V: 30V; Pitch_mm: 0.65; ContactFinish: Gold; CT: TRUE; Cert_UL: Y
J3 J5 = CMP-0002334-1: Header, 100mil, 3x1, Gold, TH; Manufacturer: Sullins Connector Solutions; CNHeader: TRUE; CT: FALSE; Green_Lifecycle: Not Set; Green_REACh: Incomplete
J4 = CMP-0075409-2: Header, 100mil, 4x1, Gold, TH; Manufacturer: Samtec; Pitch_mm: 2.54; Cert_VDE: N; Gender: Male; Cert_CSA: Y; Voltage_V: 550V; Green_REACh: Passed; Current_A: 6.3A; Green_Lifecycle: Active; Row_Count: 1
J6 = CMP-0075429-1: Header, 100mil, 16x2, Gold, TH; Manufacturer: Samtec; Pitch_mm: 2.54; Cert_VDE: N; Gender: Male; Cert_CSA: Y; Voltage_V: 550V; Green_REACh: Passed; Current_A: 6.3A; CT: False; Green_Lifecycle: Active; Row_Count: 2; CNHeader: True
L3 = CMP-0084877-1: Inductor, Ferrite Bead, Ferrite, 3 A, 120 ohm, AEC-Q200 Grade 1, SMD; Manufacturer: MuRata; SizeX_mm: 1.6; AEC Grade: 1; Value2: 3A; SizeY_mm: 0.8; SizeAreaWB_mm2: 4.68; SizeArea_mm2: 1.28; AEC Qualified: Y; AEC Category: Q200
R19 = CMP-0025925-5: RES, 47 k, 5%, 0.1 W, 0603; Manufacturer: Yageo; Power_W: 100mW; TempCo: 100 ppm/C; Value_Code: 47k0; Value: 47k; EIA_Code: E24; SizeX_mm: 1.6; SizeY_mm: 0.8; SizeZ_mm: 1; Value2: 0.1W; SizeArea_mm2: 1.28; AEC Qualified: N; VDC_V: 75V; AEC Category: Q200; SizeAreaWB_mm2: 4.68
R20 R21 = CMP-0025924-5: as R17 on sheet MD099A_DRIVER
S4 = CMP-0002196-2: Switch, Tactile, SPST, 12 V, SMD; PartNumber: 434121025816; Manufacturer: Wurth Elektronik; VDC_V: 12V; SwitchFunction: Off-On; PositionCount: 1; CurrentRating_mA: 50A
SH-J2-SH-J19 = CMP-0003623-3: as SH-J1 on sheet MD099A_CONTROL
TP16-TP20 = CMP-0055137-1: as TP5 on sheet MD099A_DRIVER
U2 = CMP-0121693-1: UART Interface IC USB Full Speed to Serial UART IC, Includes Oscillator and EEPROM, SSOP-28; Manufacturer: FTDI; SizeZ_mm: 2mm; AEC Qualified: No; Data Rate: 3Mbits/s; Interface: UART,USB; Max Supply Voltage: 5.25V; Min Supply Voltage: 1.8V; Nominal Supply Current: 7mA; Number Of Ports: 1; Standoff Height: 0.05mm; TaMax_C: +85°C; TaMin_C: -40°C; Usb Standard: USB 2.0
U3 = CMP-0043115-3: 4-Channel ESD Protection Array for High-Speed Data Interfaces, DRY0006A (USON-6); Manufacturer: Texas Instruments; IO Leakage Current(nA): 1; USB High Speed: TRUE; IO Capacitance(Typ)(pF): 1.6; Eco-Plan: Green (RoHS & no Sb/Br); IEC 61000-4-2 Contact(+/- kV): 8; Breakdown Voltage(Min)(V): 6; IEC 61000-4-2 Air-Gap(+/- kV): 12; AEC Category: Q200; AEC Qualified: N; CompType: IC; SizeAreaWB_mm2: 4.9; SizeArea_mm2: 1.45; SizeX_mm: 1.0; SizeZ_mm: 0.6; Rating: Catalog
U4 = CMP-0089204-1: CPU16 MSP430™ FRAM Microcontroller IC 16-Bit 24MHz 32KB (32K x 8) FRAM 48-LQFP (7x7); Manufacturer: Texas Instruments; Memory Type: OTHER; Data Bus Width: 16bits; Number Of Spi Channels: 4; Number Of I/Os: 44; Number Of Uart Channels: 2; AEC Qualified: No; Standoff Height: 0.05mm; Ram Size: 4KBytes; TaMin_C: -40°C; Core Architecture: RISC; Number Of Adc Channels: 12; SizeZ_mm: 1.6mm; Number Of A/D Converters: 1; Memory Size: 32KBytes; TaMax_C: +105°C; TJmax_C: +115°C; Interface: I2C,SPI,UART,USART,SCI,IrDA; Min Supply Voltage: 1.8V; Max Supply Voltage: 3.6V
Y1 = CMP-0084387-1: Resonator, 4 MHz, 39 pF, AEC-Q200 Grade 1, SMD; Manufacturer: MuRata; Load Capacitance: 39 pF; AEC Qualified: Y; TaMax_C: 125°C; AEC Category: Q200; SizeArea_mm2: 9; SizeZ_mm: 1.2; Frequency_Fixed: 4MHz; SizeAreaWB_mm2: 16.5; SizeY_mm: 2; SizeX_mm: 4.5; TaMin_C: -40°C; AEC Grade: 1

## Sheet MD099A_POWER_AND_CONNECTORS.SchDoc
size 431 x 279 mm; Date: Not shown in title block; ApprovedBy: Not shown in title block; CheckedBy: Not shown in title block; Author: Not shown in title block; CompanyName: Not shown in title block; Engineer: Not shown in title block; Organization: Not shown in title block; Address1: Not shown in title block; Address2: Not shown in title block; Address3: Not shown in title block; Address4: Not shown in title block; DocumentNumber: 5; Revision: Use project parameter SCH_Rev; SheetNumber: 4; SheetTotal: 5; PageSetup: Record=PageOptions¦CenterHorizontal=True¦CenterVertical=True¦PrintScale=1.00¦XCorrection=1.00¦YCorrection=1.00¦PrintKind=0¦BorderSize=5000000¦LeftOffset=0¦BottomOffset=0¦Orientation=2¦PaperLength=1000¦PaperWidth=1000¦Scale=100¦PaperSource=15¦PrintQuality=600¦MediaType=1¦DitherType=10¦PaperKind=Letter¦PrintScaleMode=1
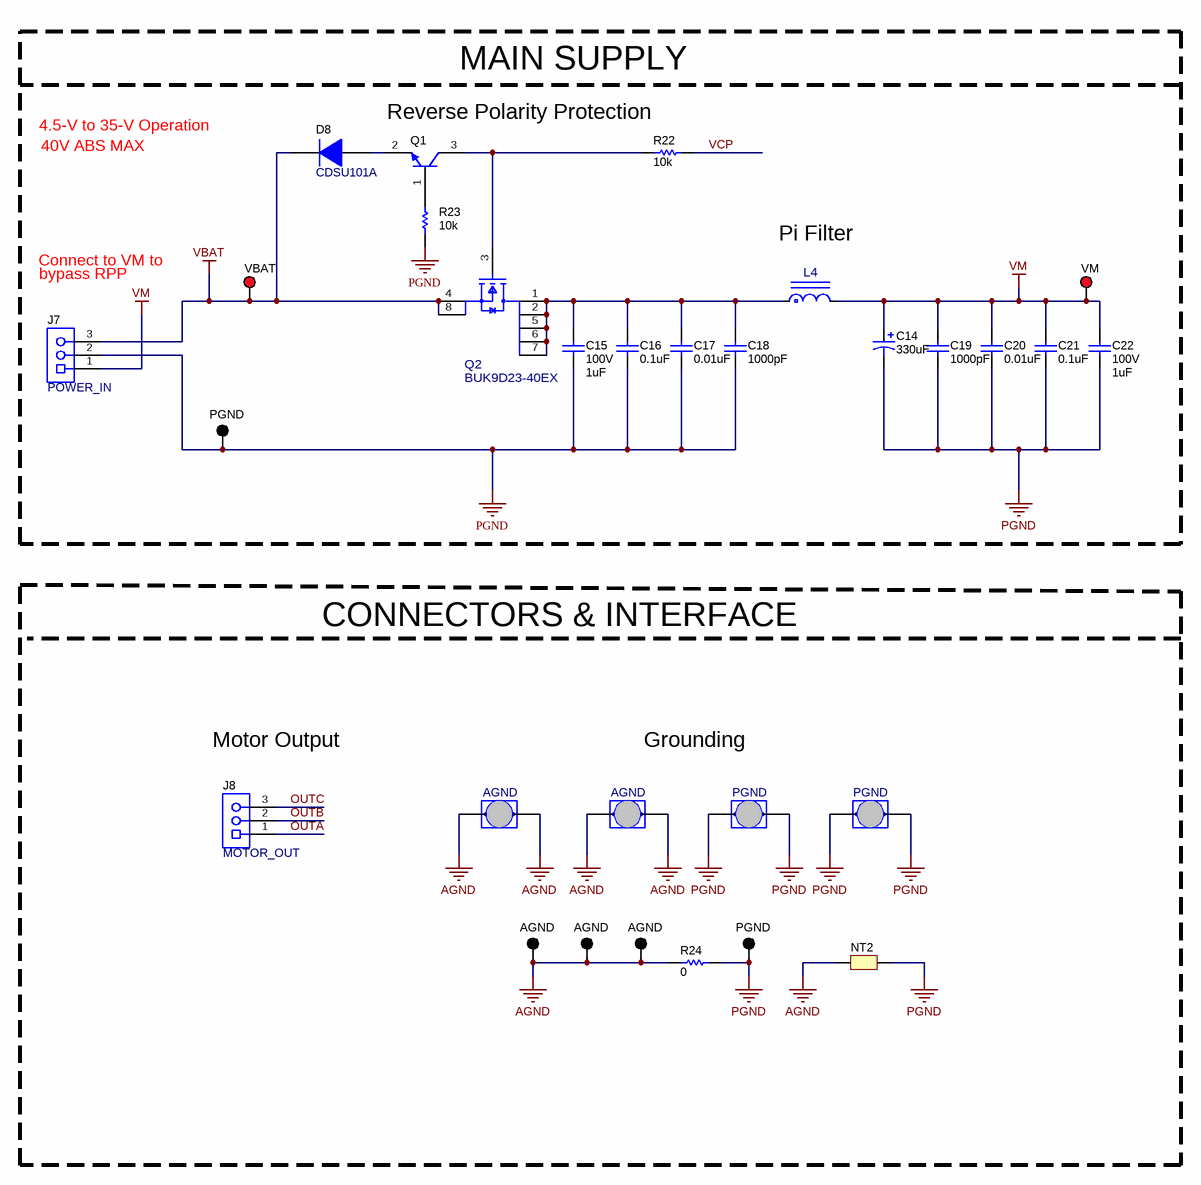
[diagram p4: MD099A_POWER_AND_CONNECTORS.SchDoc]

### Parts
C14  ValueDisplayed: 330uF  [Chemi-Con_1250x2000]  (hidden comment: ELXZ630ELL331MK20S)
C15  VDC_V: 100V  ValueDisplayed: 1uF  [1206_180]  (hidden comment: CL31B105KCHNNNE)
C16  ValueDisplayed: 0.1uF  [0603L]  (hidden comment: CGA3E3X7S2A104K080AB)
C17  ValueDisplayed: 0.01uF  [0603L]  (hidden comment: CGA3E2X7R2A103K080AA)
C18  ValueDisplayed: 1000pF  [0603L]  (hidden comment: CGA3E2X7R2A102K080AA)
C19  ValueDisplayed: 1000pF  [0603L]  (hidden comment: CGA3E2X7R2A102K080AA)
C20  ValueDisplayed: 0.01uF  [0603L]  (hidden comment: CGA3E2X7R2A103K080AA)
C21  ValueDisplayed: 0.1uF  [0603L]  (hidden comment: CGA3E3X7S2A104K080AB)
C22  VDC_V: 100V  ValueDisplayed: 1uF  [1206_180]  (hidden comment: CL31B105KCHNNNE)
D8  CDSU101A  [SOD-523F]
J7  POWER_IN  [On-Shore_ED120_3DS]
J8  MOTOR_OUT  [On-Shore_ED120_3DS]
L4  HCM1A1104V2-1R0-R  [FP-HCM1A1104V2-1R0-R_SMD2-MFG]  (value not drawn)
NT2  Net-Tie  [Net-Tie_50milWide_30milLong]  (value not drawn)  (net tie, no BOM)
Q1  FMMT620TA  [SOT-23L]  (value not drawn)
Q2  BUK9D23-40EX  [FP-BUK9D23-40EX_SOT1220-MFG]
R22  value 10k  [0603L]  (hidden comment: CRCW060310K0JNEA)
R23  value 10k  [0603L]  (hidden comment: CRCW060310K0JNEA)
R24  ValueDisplayed: 0  [1206L]  (hidden comment: RCA12060000ZSEA)
TP21  VBAT  [Keystone5005]
TP22  VM  [Keystone5005]
TP23  PGND  [Keystone5001]
TP24  AGND  [Harwin_D3082-05]
TP25  AGND  [Harwin_D3082-05]
TP26  PGND  [Harwin_D3082-05]
TP27  PGND  [Harwin_D3082-05]
TP28  AGND  [Keystone5001]
TP29  AGND  [Keystone5001]
TP30  AGND  [Keystone5001]
TP31  PGND  [Keystone5001]

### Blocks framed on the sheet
MAIN SUPPLY: C14-C22 D8 J7 L4 Q1 Q2 R22 R23 TP21-TP23
CONNECTORS & INTERFACE: J8 NT2 R24 TP24-TP31

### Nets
AGND: NT2.1 R24.1 TP24.1 TP24.2 TP25.1 TP25.2 TP28.1 TP29.1 TP30.1
PGND: C14.2(-) C15.2 C16.2 C17.2 C18.2 C19.2 C20.2 C21.2 C22.2 J7.2 NT2.2 R23.2 R24.2 TP23.1 TP26.1 TP26.2 TP27.1 TP27.2 TP31.1
VBAT: D8.1(K) J7.3 Q2.4(S) Q2.8(S) TP21.1
VM: C14.1(+) C19.1 C20.1 C21.1 C22.1 J7.1 L4.2 TP22.1
OUTA: J8.1
OUTB: J8.2
OUTC: J8.3
VCP: R22.1
NetC15_1: C15.1 C16.1 C17.1 C18.1 L4.1 Q2.1(D) Q2.2(D) Q2.5(D) Q2.6(D) Q2.7(D)
NetD8_2: D8.2(A) Q1.2(E)
NetQ1_1: Q1.1(B) R23.1
NetQ1_3: Q1.3(C) Q2.3(G) R22.2

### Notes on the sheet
- 40V ABS MAX
- 4.5-V to 35-V Operation
- Reverse Polarity Protection
- bypass RPP
- Connect to VM to
- Pi Filter
- Motor Output
- Grounding

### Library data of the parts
C14 = CMP-0009912-2: CAP, AL, 330 uF, 63 V, +/- 20%, AEC-Q200 Grade 2, TH; Manufacturer: Chemi-Con; Polarized: Y; CompType: Capacitor; Value: 330uF; U/M: EA; Cap_F: 330µF; Value1: Unknown; VDC_V: 63V; IRMS_A: 1.29A; TaMin_C: -55°C; TaMax_C: 105°C; Cap_Case: 12.5x20mm; AEC Category: Q200; AEC Grade: 2; SizeAreaWB_mm2: 210.25; SizeArea_mm2: 156.25; SizeX_mm: 12.5; SizeZ_mm: 21.5
C15 C22 = CMP-0008801-2: CAP, CERM, 1 uF, 100 V, +/- 10%, X7R, 1206; Manufacturer: Samsung; TaMin_C: -55°C; Polarized: N; SizeAreaWB_mm2: 10.92; Value1: Unknown; U/M: EA; Value: 1uF; TaMax_C: 125°C; SizeZ_mm: 1.8; SizeX_mm: 3.2; SizeY_mm: 1.6; Cap_Case: 1206; SizeArea_mm2: 5.12; Cap_F: 1µF; AEC Category: Q200
C16 C21 = CMP-0007099-4: CAP, CERM, 0.1 uF, 100 V, +/- 10%, X7S, AEC-Q200 Grade 1, 0603; Manufacturer: TDK; Polarized: N; Value: 0.1uF; U/M: EA; Cap_F: 100nF; ESR_ohm: 0.04959; Value1: 0.04959 ohm; VDC_V: 100V; IRMS_A: 751.618mA; TaMin_C: -55°C; TaMax_C: 125°C; Cap_Case: 0603; AEC Category: Q200; AEC Qualified: Y; AEC Grade: 1; SizeAreaWB_mm2: 4.68; SizeX_mm: 1.6; SizeY_mm: 0.8; SizeArea_mm2: 1.28
C17 C20 = CMP-0007082-4: CAP, CERM, 0.01 uF, 100 V, +/- 10%, X7R, AEC-Q200 Grade 1, 0603; Manufacturer: TDK; Polarized: N; Value: 0.01uF; U/M: EA; Cap_F: 10nF; ESR_ohm: 0.235428; Value1: 0.235428 ohm; VDC_V: 100V; IRMS_A: 396.995mA; TaMin_C: -55°C; TaMax_C: 125°C; Cap_Case: 0603; AEC Category: Q200; AEC Qualified: Y; AEC Grade: 1; SizeArea_mm2: 1.28; SizeAreaWB_mm2: 4.68; SizeX_mm: 1.6; SizeY_mm: 0.8
C18 C19 = CMP-0007081-4: CAP, CERM, 1000 pF, 100 V, +/- 10%, X7R, AEC-Q200 Grade 1, 0603; Manufacturer: TDK; Polarized: N; Value: 1000pF; U/M: EA; Cap_F: 1nF; ESR_ohm: 1.97137; Value1: 1.97137 ohm; VDC_V: 100V; IRMS_A: 305.705mA; TaMin_C: -55°C; TaMax_C: 125°C; Cap_Case: 0603; AEC Category: Q200; AEC Qualified: Y; AEC Grade: 1; SizeArea_mm2: 1.28; SizeAreaWB_mm2: 4.68; SizeX_mm: 1.6; SizeY_mm: 0.8
D8 = CMP-0076943-3: Diode, Switching, 90 V, 0.1 A, SOD-523F; Manufacturer: Comchip Technology; SizeAreaWB_mm2: 5.13; Vr_V: 90V; SizeArea_mm2: 1.53; TJmax_C: 125°C; AEC Category: Q101; Value: 90V; SizeZ_mm: 0.85; Green_REACh: Incomplete; Io_A: 100mA; Vf_V: 1V; SizeY_mm: 0.9; Green_Lifecycle: Not Set; Value1: 0.1A; SizeX_mm: 1.7; MFG_Status: TI_Obsolete
J7 J8 = CMP-0074911-1: Terminal Block, 5.08 mm, 3x1, Brass, TH; Manufacturer: On-Shore Technology; PartNumber: ED120/3DS; Cert_VDE: Y; CNHeader: False; Current_A: 15A; Green_Lifecycle: Not Set; Shrouded: N; Gender: Female; Green_REACh: Incomplete; Voltage_V: 300V; Row_Count: 1; Pitch_mm: 5.08; CT: True
L4 = CMP-0094173-1: 1 µH Shielded - Inductor 19 A 3.1mOhm Max Nonstandard; Manufacturer: Eaton; Isat: 25A; Irms: 19A; DCR_ohm: 3.1m; Material: Alloy powder; Value: 1uH; SizeZ_mm: 4mm; Ind_H: 1µH; AEC Qualified: Yes; AEC Grade: Grade 0; Shrouded: true; Test Frequency: 100kHz; Self Resonant Frequency: 38MHz; Tolerance_%: 20%
NT2 = CMP-0078142-4: Single point connection between nets.
Q1 = CMP-0000467-2: Transistor, NPN, 80 V, 1.5 A, AEC-Q101, SOT-23; Manufacturer: Diodes Inc.; TaMax_C: 150°C; Value2: 900; Value1: 1.5 A; Vcesat1_V: 160mV; SizeX_mm: 2.5; SizeY_mm: 3; TaMin_C: -55°C; IcRated_A: 1.5A; CompType: BJT; SizeZ_mm: 1.1; AEC Qualified: Y; Value: 80 V; SizeArea_mm2: 7.5; NPN: 1; Vceo_V: 80V; PNP: 0; AEC Category: Q101; SizeAreaWB_mm2: 14; U/M: EA
Q2 = CMP-0088880-1: N-Channel 40V 8A (Ta) 15W (Tc) Surface Mount DFN2020MD-6; Manufacturer: Nexperia; Reverse Recovery Charge: 5.3nC; Vgs_V: 15V; Rthja Max: 57K/W; Number Of N Channels: 1; Pulse Drain Current: 76A; Threshold Vgs Max: 2.1V; Power_W: 2.3W; Reverse Recovery Time: 12.9ns; TaMin_C: -55°C; Rdson45_ohm: 0.018; SizeZ_mm: 0.65mm; ChMode: False; Transconductance: 39S; AEC Qualified: Yes; Typ Forward Diode Voltage: 0.8V; Turn Off Delay Time: 12ns; TaMax_C: +175°C; Input Capacitace At Vds: 637pF @ 20V; QgTyp_nC: 11.5nC @ 10V; Threshold Vgs Min: 1.4V; AEC Grade: Grade 0; VdsMax_V: 1.2V; Turn On Delay Time: 2ns
R22 R23 = CMP-0025701-4: RES, 10 k, 5%, 0.1 W, AEC-Q200 Grade 0, 0603; Manufacturer: Vishay-Dale; Value_Code: 10k0; Power_W: 100mW; Value2: 0.1W; VDC_V: 75V; TempCo: 200 ppm/C; EIA_Code: E24; AEC Category: Q200; AEC Qualified: Y; AEC Grade: 0; SizeArea_mm2: 1.28; SizeX_mm: 1.6; SizeY_mm: 0.8; SizeZ_mm: 1
R24 = CMP-0018760-2: RES, 0, 5%, 0.25 W, AEC-Q200 Grade 0, 1206; Manufacturer: Vishay-Dale; Power_W: 250mW; TempCo: ppm/C; Value_Code: 0000; U/M: EA; Value: 0; EIA_Code: E24; SizeX_mm: 3.2; SizeY_mm: 1.6; SizeZ_mm: 1.35; Value2: 0.25W; SizeArea_mm2: 5.12; AEC Qualified: Y; AEC Category: Q200
TP21 TP22 = CMP-0055142-1: Test Point, Compact, Red, TH; Manufacturer: Keystone; CNHeader: FALSE; ContactFinish: Silver; CT: TRUE; Green_Lifecycle: Active; Green_REACh: Passed
TP23 TP28-TP31 = CMP-0055138-1: Test Point, Miniature, Black, TH; Manufacturer: Keystone; CNHeader: FALSE; Green_Lifecycle: Active; Green_REACh: Passed; ContactFinish: Silver; CT: TRUE
TP24-TP27 = CMP-0075110-1: 1mm Uninsulated Shorting Plug, 10.16mm spacing, TH; Manufacturer: Harwin; PartNumber: D3082-05; CNHeader: False; Green_Lifecycle: Active; Green_REACh: Passed; CompType: Jumper Wire

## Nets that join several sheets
AGND: MD099A_CONTROL (R4.3 R6.1 R7.1 R8.1), MD099A_DRIVER (9 pins), MD099A_INTERFACE (25 pins), MD099A_POWER_AND_CONNECTORS (9 pins)
AVDD: MD099A_CONTROL (R1.2 R2.2 R3.2 R4.1), MD099A_DRIVER (6 pins)
PGND: MD099A_DRIVER (5 pins), MD099A_POWER_AND_CONNECTORS (19 pins)
VBK: MD099A_DRIVER (8 pins), MD099A_INTERFACE (J6.3)
VM: MD099A_DRIVER (6 pins), MD099A_POWER_AND_CONNECTORS (8 pins)
ALARM: MD099A_DRIVER (D3.1 U1.30), MD099A_INTERFACE (J6.9)
BRAKE: MD099A_DRIVER (U1.28), MD099A_INTERFACE (J6.27)
BRAKE_SW: MD099A_CONTROL (S1.2 TP1.1), MD099A_INTERFACE (J6.28)
DACOUT: MD099A_DRIVER (TP12.1 U1.29), MD099A_INTERFACE (J6.15)
DIR: MD099A_DRIVER (U1.27), MD099A_INTERFACE (J6.29)
DIR_SW: MD099A_CONTROL (S2.2 TP2.1), MD099A_INTERFACE (J6.30)
DRVOFF: MD099A_DRIVER (U1.18), MD099A_INTERFACE (J6.31)
DRVOFF_SW: MD099A_CONTROL (S3.2 TP3.1), MD099A_INTERFACE (J6.32)
FG: MD099A_DRIVER (R9.1 TP13.1 U1.22), MD099A_INTERFACE (J6.5)
MCX_SCL: MD099A_DRIVER (R10.2 R12.1), MD099A_INTERFACE (J6.23)
MCX_SDA: MD099A_DRIVER (R11.2 R13.1), MD099A_INTERFACE (J6.21)
MSP_PWM: MD099A_CONTROL (J1.2), MD099A_INTERFACE (U4.42)
nFAULT: MD099A_DRIVER (R16.1 U1.31), MD099A_INTERFACE (J6.7)
OUTA: MD099A_DRIVER (TP7.1 U1.11 U1.12), MD099A_POWER_AND_CONNECTORS (J8.1)
OUTB: MD099A_DRIVER (TP8.1 U1.13 U1.14), MD099A_POWER_AND_CONNECTORS (J8.2)
OUTC: MD099A_DRIVER (TP9.1 U1.15 U1.16), MD099A_POWER_AND_CONNECTORS (J8.3)
POT: MD099A_CONTROL (J1.4 R5.1), MD099A_INTERFACE (U4.43)
SPEED: MD099A_DRIVER (U1.21), MD099A_INTERFACE (J6.25)
SPEED_IN: MD099A_CONTROL (J1.1 J1.3 J1.5), MD099A_INTERFACE (J6.26)
VCP: MD099A_DRIVER (C1.1 U1.7), MD099A_POWER_AND_CONNECTORS (R22.1)

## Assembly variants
001: not fitted L1 L2 R15 R16 R17 R18 R19 R20 R21 R22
